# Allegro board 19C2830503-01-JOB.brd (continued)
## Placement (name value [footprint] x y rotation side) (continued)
C715  0.1uF  [C0402]  70.59 68.93 0 bottom
C716  0.1uF  [C0402]  47.24 68.58 270 bottom
C717  0.1uF  [C0402]  47.24 69.85 270 bottom
C718  27pF  [C0402]  152.53 66.67 270 bottom
C719  27pF  [C0402]  148.46 66.67 90 bottom
C720  0.1uF  [C0402]  144.02 131.57 0 bottom
C721  47uF  [C0805]  28.7 65.66 270 bottom
C722  1000pF  [C0402]  20.95 71.75 180 top
C723  0.1uF  [C0402]  22.23 71.75 0 top
C724  1uF  [C0603]  12.19 59.44 90 bottom
C725  0.1uF  [C0402]  89.41 56.39 0 bottom
C726  0.1uF  [C0402]  88.01 56.39 0 bottom
C727  100uF  [C1206-1]  31.75 60.71 270 bottom
C728  470uF  [C_2P_244_287X177_H110]  27.69 61.09 0 top
C729  1uF  [C0603]  13.21 58.04 270 top
C730  0.1uF  [C0402]  145.85 57.86 270 top
C731  1uF  [C0603]  13.21 56.52 270 top
C732  0.1uF  [C0402]  34.04 52.96 0 bottom
C733  2.2uF  [C0603]  113.03 50.42 180 bottom
C734  0.1uF  [C0402]  114.55 50.16 180 bottom
C735  0.1uF  [C0402]  61.09 49.4 270 bottom
C736  0.1uF  [C0402]  72.34 49.28 270 bottom
C737  0.1uF  [C0402]  64.85 48.77 90 bottom
C738  0.1uF  [C0402]  49.66 48.39 270 bottom
C739  0.1uF  [C0402]  41.53 47.62 180 bottom
C740  0.1uF  [C0402]  53.47 47.75 180 bottom
C741  0.1uF  [C0402]  126.27 47.25 180 bottom
C742  0.1uF  [C0402]  97.41 47.12 0 bottom
C743  0.1uF  [C0402]  88.27 47.12 0 bottom
C744  0.1uF  [C0402]  85.6 47.12 0 bottom
C745  0.1uF  [C0603]  22.35 47.12 270 bottom
C746  0.1uF  [C0402]  75.9 46.29 180 bottom
C747  0.1uF  [C0402]  53.34 45.85 180 bottom
C748  0.1uF  [C0402]  41.53 45.59 180 bottom
C749  0.1uF  [C0603]  128.4 45.21 90 bottom
C750  0.1uF  [C0402]  97.28 45.09 180 bottom
C751  0.1uF  [C0402]  88.27 44.83 0 bottom
C752  0.1uF  [C0402]  85.72 44.76 180 bottom
C753  0.1uF  [C0402]  105.79 44.07 270 bottom
C754  0.1uF  [C0402]  53.34 44.01 0 bottom
C755  0.1uF  [C0402]  64.85 43.94 0 bottom
C756  0.01uF  [C0402]  102.62 43.56 90 bottom
C757  0.01uF  [C0402]  100.33 43.56 270 bottom
C758  0.1uF  [C0402]  75.9 44.07 180 bottom
C759  0.1uF  [C0402]  62.23 43.31 0 bottom
C760  0.1uF  [C0402]  64.64 42.24 270 bottom
C761  0.01uF  [C0402]  102.62 42.16 90 bottom
C762  47uF  [C0805]  110.62 42.04 270 bottom
C763  0.1uF  [C0402]  49.73 41.91 270 bottom
C764  0.01uF  [C0402]  38.86 40.77 270 bottom
C765  100uF  [C1206-1]  116.97 41.27 0 bottom
C766  0.01uF  [C0402]  102.62 40.77 90 bottom
C767  4.7uF  [C1206-1]  125.6 39.75 90 bottom
C768  0.1uF  [C0402]  41.27 39.75 90 bottom
C769  0.1uF  [C0402]  33.15 39.75 90 bottom
C770  0.1uF  [C0402]  84.18 39.67 270 bottom
C771  0.1uF  [C0402]  72.11 39.67 270 bottom
C772  0.1uF  [C0402]  95.99 39.65 270 bottom
C773  47uF  [C0805]  110.62 39.62 270 bottom
C774  0.1uF  [C0402]  54.99 39.43 180 bottom
C775  1uF  [C0603]  131.44 41.53 90 bottom
C776  0.1uF  [C0402]  143 40.89 180 bottom
C777  0.1uF  [C0402]  73.99 38.42 0 bottom
C778  10uF  [C0603]  41.27 38.1 90 bottom
C779  47uF  [C0805]  110.62 37.21 270 bottom
C780  22uF  [C0805]  88.65 37.21 0 bottom
C781  22uF  [C0805]  76.96 37.21 0 bottom
C782  0.1uF  [C0402]  85.72 37.08 0 bottom
C783  0.1uF  [C0402]  33.15 36.96 90 bottom
C784  0.01uF  [C0402]  102.62 36.58 90 bottom
C785  22uF  [C0805]  52.83 36.45 0 bottom
C786  22uF  [C0805]  49.4 36.2 0 bottom
C787  10uF  [C0603]  41.27 36.32 90 bottom
C788  0.1uF  [C0402]  74.24 36.13 180 bottom
C789  22uF  [C0805]  65.48 35.94 0 bottom
C790  0.1uF  [C0402]  96.39 35.81 270 bottom
C791  0.22uF  [C0603]  126.49 35.43 0 bottom
C792  2.2uF  [C0603]  32.77 35.43 270 bottom
C793  0.1uF  [C0402]  102.62 35.18 270 bottom
C794  0.01uF  [C0402]  102.62 33.78 90 bottom
C795  470uF  [C_2P_244_287X177_H110]  109.09 33.53 90 bottom
C796  20pF  [C0402]  66.17 111.51 180 top
C797  20pF  [C0402]  63.37 111.51 0 top
C798  10uF  [C0603]  134.21 80.34 180 top
C799  0.1uF  [C0402]  132.56 79.96 0 top
C800  1uF  [C0402]  129.9 69.8 0 top
C801  22uF  [C0805]  132.46 69.72 270 top
C802  0.1uF  [C0402]  54.05 109.55 180 top
C803  0.01uF  [C0402]  55.73 109.8 90 top
C804  1000pF  [C0402]  55.73 108.41 270 top
C805  0.1uF  [C0402]  67.56 113.54 180 top
C806  0.01uF  [C0402]  68.96 113.54 180 top
C807  1000pF  [C0402]  70.36 113.54 0 top
C808  0.1uF  [C0402]  67.31 108.71 0 bottom
C809  0.01uF  [C0402]  68.58 108.71 0 bottom
C810  1000pF  [C0402]  65.91 108.71 180 bottom
C811  0.01uF  [C0402]  67.56 111.51 0 top
C812  0.1uF  [C0402]  68.96 111.51 0 top
C813  1000pF  [C0402]  70.36 111.51 180 top
C814  330pF  [C0402]  54.48 148.59 90 bottom
C815  330pF  [C0402]  130.45 32.38 270 bottom
C816  0.01uF  [C0402]  65.35 96.9 0 bottom
C817  0.01uF  [C0402]  78.23 84.33 270 bottom
C818  0.01uF  [C0402]  77.67 75.95 180 bottom
C819  0.01uF  [C0402]  39.37 67.69 270 top
C820  0.01uF  [C0402]  65.94 75.39 90 bottom
C821  0.01uF  [C0402]  80.77 85.98 270 bottom
C822  0.01uF  [C0402]  80.77 90.93 270 bottom
C823  0.01uF  [C0402]  78.74 89.15 90 bottom
C825  0.01uF  [C0402]  69.72 74.96 0 bottom
C826  0.01uF  [C0402]  68.02 75.49 90 bottom
C827  0.1uF  [C0402]  171.58 147.96 0 top
C828  10pF  [C0402]  169.8 155.57 90 top
C829  0.01uF  [C0402]  55.75 138.05 270 top
C830  0.01uF  [C0402]  131.06 43.05 90 bottom
C831  220uF  [C_2P_114_138X118]  73.03 138.56 0 bottom
C832  1000uF  [C_2P_244_295X177]  115.54 135.89 90 bottom
C833  220uF  [C_2P_114_138X118]  106.83 53.9 180 top
C834  220uF  [C_2P_114_138X118]  39.27 33.43 180 bottom
C835  0.1uF  [C0402]  29.72 134.37 270 bottom
C836  0.1uF  [C0402]  43.18 134.49 270 bottom
C837  0.1uF  [C0402]  30.48 146.3 270 bottom
C838  0.1uF  [C0402]  43.03 126.9 270 bottom
C839  0.1uF  [C0402]  162.05 107.31 270 top
C840  0.1uF  [C0402]  162.05 105.92 270 top
C841  1uF  [C0402]  31.14 128.4 90 bottom
C842  1uF  [C0402]  43.81 142.49 0 bottom
C843  0.1uF  [C0402]  43 147.57 0 top
C844  0.1uF  [C0402]  156.62 102.26 180 bottom
CN1  POWER MODULE_5223957-3  [POWERMODULE_2P_5223957-3]  27.5 169.96 270 top
CN2  PH_3x1V_2.00mm  [HD_3X1P_79_D]  169.67 128.65 270 top
CN3  BB_60x2V_S0.5mm  [BB_60X2P_20_2225X285_F]  35.32 144.45 90 top
CN4  COAXIEL_3V  [HS_UFL-R-SMT-1]  73.84 129.41 180 top
CN5  COAXIEL_3V  [HS_UFL-R-SMT-1]  47.5 138.56 270 top
CN6  COAXIEL_3V  [HS_UFL-R-SMT-1]  47.5 143.13 270 top
CN7  PH_6x1V_2.00mm  [HD_6X1P_79_D]  153.16 128.78 90 top
CN8  PH_3x1V_2.00mm  [HD_3X1P_79_D]  167 147.83 90 top
CN9  PH_2x1V_2.00mm  [HD_2X1P_79_H236_D]  146.81 124.59 90 top
CN10  COAXIEL_3V  [HS_UFL-R-SMT-1]  60.35 119.13 0 top
CN11  COAXIEL_4V  [COAXIAL_4P_MM8030-2610]  96.98 125.73 180 top
CN12  COAXIEL_4V  [COAXIAL_4P_MM8030-2610]  100.03 125.73 180 top
CN13  COAXIEL_4V  [COAXIAL_4P_MM8030-2610]  56.9 124.59 180 top
CN15  PH_2x1V_2.00mm  [HD_2X1P_79_H236_D]  74.8 120.02 270 top
CN16  RJ45_2x1_W/XFMR&LED  [RJ45_28P_RTB-19GB9J1A]  170.74 85.7 90 top
CN17  PH_4x2V_2.54mm  [HD_4X2P_100_D]  22.4 57.66 270 top
CN18  RF_5H  [RF-SMAC037]  177.1 40.71 90 top
CN19  PH_4x1V_2.0mm  [HD_4X1P_79_H264]  26.67 33.91 0 top
CN20  PH_4x1V_2.0mm  [HD_4X1P_79_H264]  35.31 33.91 0 top
CN21  PH_3x1V_2.54mm  [HD_3X1P_100_H320_D]  142.75 32.77 0 top
CN22  PH_5x2V_S1.27mm  [HD_5X2P_50_H235]  159.89 39.12 0 top
CN23  COAXIEL_3V  [HS_UFL-R-SMT-1]  73.84 124.84 0 top
CN24  PH_2x1V_2.00mm  [HD_2X1P_79_H236_D]  173.23 151.89 90 top
D1  TPD4S012DRYR  [SON_6P_20_59X39]  169.16 164.72 270 top
D3  KPA-1606EC  [LED_2P_KPA-1606EC]  179.2 157.82 270 top
D4  KP-1608MGC  [LED_0603]  170.69 157.75 90 top
D5  KPA-1606QBC-D  [LED_2P_KPA-1606QBC-D]  179.2 154.14 270 top
D6  KP-1608EC  [LED_0603]  175.01 140.22 270 top
D7  NL/SBU05U20LPS-7  [DIODE_2P_36_40X27]  111.12 116.33 270 top
D8  BZX84-C12  [SOT-23]  21.72 50.29 180 top
D9  PMEG1020EH  [DIODE_2P_146_106X61_ANODE2]  136.91 109.09 180 bottom
D10  ASD500V  [DIODE_2P_78_79X55]  11.01 36.69 90 top
D11  PMEG1020EH  [DIODE_2P_146_106X61_ANODE2]  148.97 158.62 0 bottom
D14  TPD2EUSB30DRTR  [SOT_TPD2EUSB30DRTR]  161.95 111.81 270 bottom
DBG_D1  KPBA-3010ESGC  [LED_2P_KPBA-3010ESGC]  179.01 149.76 90 top
DBG_D2  KPA-1606QBC-D  [LED_2P_KPA-1606QBC-D]  179.2 145 270 top
DBG_D3  KPA-1606QBC-D  [LED_2P_KPA-1606QBC-D]  179.2 141.06 270 top
DC_IN1  JACK_3H  [PJ_3P_2DC-0005]  16.64 44.96 270 top
DIMM1  SODIMMDDR3_204  [DDR3_204P_DDRSK-20401-TP65]  117.6 78.7 90 top
EEPROM1  ST_M24M01-RMN6TP  [SOIC_8P_50_193X236]  129.29 100.33 90 top
EMU1  BB_60V_S0.5mm  [BB_30X2P_20_838X285_F]  96.77 145.93 270 top
ESD1  -  [AMC-ESD-B]  160 175.36 0 top
FAN1  WB_4V_2.00mm  [WF_4P_79_BOX_D_721-81-04TW0]  16.44 57.28 270 top
FM1  Fiducial  [FIDUCIAL]  28.59 163.97 0 top
FM2  Fiducial  [FIDUCIAL]  167.65 36.95 0 top
FM3  Fiducial  [FIDUCIAL]  28.57 163.96 180 bottom
FM4  Fiducial  [FIDUCIAL]  167.64 36.96 180 bottom
FTDI_USB  MINIUSB_5H  [USB-UH51543]  174.54 165.39 90 top
GPS1  GNS_TC6000G  [BGA_36P_60_394X366]  147.07 43.49 90 top
H1  -  [H35P7-MTH]  138.89 166.98 0 top
H2  -  [H35P7-MTH]  138.89 124.49 0 top
H7  H107x17-NPTH  [H107X17-NPTH]  159 34.01 0 top
H8  -  [H27P35-MTH]  176.85 32.46 0 top
J1  ATCA_160H  [ATCA_160P_384312]  7.9 127.06 270 top
J2  ATCA_160H  [ATCA_160P_384312]  7.9 152.06 270 top
L1  22uH  [INDUCTOR_2P_267_270X265]  116.2 162.56 0 top
L2  3.3uH  [CHOKE_2P_238_287X260]  128.52 161.06 180 top
L3  0.47uH  [CHOKE_2P_238_287X260]  128.24 145.44 180 top
L4  0.2uH  [CHOKE_2P_238_287X260]  65.15 146.94 0 top
L5  0.47uH  [CHOKE_2P_238_287X260]  78.18 137.82 90 top
L6  0.47uH  [CHOKE_2P_238_287X260]  85.6 137.79 90 top
L7  0.47uH  [CHOKE_2P_238_287X260]  26.29 102.24 180 top
L8  3.3uH  [CHOKE_2P_238_287X260]  26.29 94.87 180 top
L9  1.5uH  [INDUCTOR_2P_183_205X193]  29.34 69.6 0 top
L10  0.082uH  [L0603]  171.83 43.31 180 top
L11  3.6nH  [L0402]  169.93 39.24 0 top
L12  0.47uH  [CHOKE_2P_238_287X260]  119.51 35.31 0 top
LCD1  LCD-Module_17P  [LCD_17P_NHD-C12832A1Z]  65.91 163.32 0 top
MCU  W_4V_2.54mm  [WF_4P_100_D_744-81-04TW20]  157.86 126.92 270 top
NAND1  MICRON_MT29F4G08ABBDAHC:D  [BGA_63P_31_512X413_C14]  38.58 157.84 0 bottom
NOR1  NUMONYX_N25Q128A11ESF40F  [SOIC_16P_50_406X406]  141.15 138.56 180 bottom
NOREF  -  []  37.72 18.29 0 top
NOREF#2  -  []  89.87 32.87 180 bottom
NOREF#3  -  []  174.24 64.52 180 bottom
NOREF#4  -  []  149.5 37 180 bottom
NOREF#5  -  []  166.75 65.53 180 bottom
NOREF#6  -  []  168.02 57.66 180 bottom
OSC1  32.768KHz  [OSC-4SD]  168.53 138.56 180 top
OSC2  25MHz  [OSC_6P_50_203X132]  102.36 117.6 90 top
OSC3  19.2MHz_15pF  [OSC_4P_236X157_382X295_H161]  52.45 118.49 0 top
OSC4  32.768KHz  [OSC-4SD]  144.65 53.59 0 top
PB1  30_100MHz  [L0805]  162 118.08 270 top
PHY1  MARVELL_88E1111-B2-BAB1C000  [BGA_117P_39_551X394]  144.15 74.1 0 bottom
PHY2  MARVELL_88E1111-B2-BAB1C000  [BGA_117P_39_551X394]  144.15 98.49 0 bottom
PMBUS1  PH_5x1V_2.54mm  [HD_5X1P_100_D]  149.86 129.03 90 top
PWR  DTSA-63R-V  [SW_2P_DTSA-63K-V_D]  176.75 134.16 90 top
Q1  TI_TPS73701DRBT  [QFN_8P_26_118X118]  165.74 169.67 0 top
Q2  TI_TPS74701DRCT  [QFN10P_20_118X118_TP94X65V5]  108.33 163.45 0 top
Q3  MMBT3904LT1G  [SOT-23]  176.46 156.62 90 top
Q4  MMBT3904LT1G  [SOT-23]  176.47 152.11 270 top
Q5  MMBT3904LT1G  [SOT-23]  176.6 143.86 270 top
Q6  MICROCHIP_MCP9700AT-E/LT  [SC-70_5P]  121.28 118.36 180 top
Q7  TI_TPS73701DRBT  [QFN_8P_26_118X118]  143.26 115.44 0 top
Q8  TI_TPS73701DRBT  [QFN_8P_26_118X118]  149.99 115.44 0 top
Q9  MMBT3904LT1G  [SOT-23]  25.4 47.62 90 top
Q10  TLV1117-33CDCY  [SOT-223]  120.02 171.63 0 bottom
Q11  MMBT3904LT1G  [SOT-23]  177.1 158.4 90 bottom
Q12  MMBT3904LT1G  [SOT-23]  173.55 157.51 90 bottom
Q13  APL431LBAI-TRG  [SOT-23]  78.61 158.67 0 bottom
Q14  MMBT3904LT1G  [SOT-23]  177.61 151.92 90 bottom
Q15  MICROCHIP_MCP9700AT-E/LT  [SC-70_5P]  124.94 150.5 90 bottom
Q16  MMBT3904LT1G  [SOT-23]  177.48 145.64 270 bottom
Q17  MICROCHIP_MCP9700AT-E/LT  [SC-70_5P]  68.45 143.64 0 bottom
Q18  MMBT3904LT1G  [SOT-23]  175.3 142.21 270 bottom
Q19  SI4435DDY-T1-GE3  [SOIC_8P_50_193X236]  11.81 50.42 0 top
Q20  2N7002  [SOT-23]  21.72 49.66 180 bottom
Q21  MICROCHIP_MCP9700AT-E/LT  [SC-70_5P]  116.92 34.04 180 bottom
R1  10M  [R1206]  38.48 174.5 90 top
R2  10M  [R1206]  150.5 174.5 270 top
R3  1K  [R0402]  162.23 171.04 90 bottom
R4  10K  [R0402]  163.58 171.02 270 bottom
R5  NL/0  [R0402]  153.92 174.12 90 top
R6  NL/0  [R0402]  155.32 174.12 90 top
R7  10K  [R0402]  104.39 173.99 0 top
R8  82.5K  [R0603]  113.67 173.99 0 top
R9  0  [R0402]  143.74 172.47 180 top
R10  1.87K  [R0603]  105.03 172.34 270 top
R11  10K  [R0402]  113.79 171.45 0 top
R12  22  [R0402]  133.32 171.42 270 top
R13  31.6K  [R0402]  124.84 170.69 270 top
R14  10K  [R0402]  126.24 170.69 90 top
R15  56.2K  [R0402]  133.32 169.52 90 top
R16  1K  [R0402]  160.66 169.16 180 top
R17  22.6K  [R0603]  105.03 170.69 270 top
R18  0  [R0402]  108.71 168.15 270 top
R19  17.4K  [R0402]  164.85 166.5 0 top
R20  10K  [R0402]  166.75 166.5 180 top
R21  10K  [R0402]  133.32 167.59 270 top
R22  1.69K  [R0603]  125.6 167 270 top
R23  3.57K  [R0603]  104.9 166.88 270 top
R24  10K  [R0402]  173.23 155.07 0 top
R25  1K  [R0402]  43.81 162.69 180 top
R26  0  [R0402]  168.66 161.93 0 top
R27  22  [R0402]  43.81 161.29 0 top
R28  10K  [R0402]  109.35 159.66 270 top
R29  4.7K  [R0402]  43.81 159.51 180 top
R30  56  [R0402]  177.8 158.69 90 top
R31  510  [R0402]  175.13 158.57 90 top
R32  100  [R0402]  88.52 157.48 180 top
R33  100  [R0402]  90.83 157.35 0 top
R34  4.7K  [R0402]  27.58 156.74 180 top
R35  0  [R0402]  29.57 156.74 180 top
R36  4.7K  [R0402]  88.52 155.96 0 top
R37  10  [R0402]  90.83 155.96 0 top
R38  4.7K  [R0402]  102.49 155.96 0 top
R39  0  [R0402]  165.86 155.57 180 top
R40  10K  [R0402]  167.89 155.57 0 top
R41  0  [R0402]  29.57 155.42 180 top
R42  4.7K  [R0402]  88.52 154.56 0 top
R43  10  [R0402]  90.83 154.56 0 top
R44  10  [R0402]  102.49 154.56 180 top
R45  0  [R0402]  165.86 152.78 180 top
R46  0  [R0402]  167.89 154.18 180 top
R47  10  [R0402]  90.81 153.29 0 top
R48  4.7K  [R0402]  134.75 153.29 0 top
R49  10  [R0402]  102.49 153.16 180 top
R50  4.7K  [R0402]  105.16 153.16 180 top
R51  0  [R0402]  165.86 154.18 180 top
R52  0  [R0402]  167.89 152.78 0 top
R53  10  [R0402]  88.52 151.89 180 top
R54  0  [R0402]  90.81 151.89 180 top
R55  10  [R0402]  41.4 152.4 180 top
R56  4.7K  [R0402]  102.49 151.77 0 top
R57  10  [R0402]  105.16 151.77 180 top
R58  4.75K  [R0402]  107.19 151.77 180 top
R59  10K  [R0402]  169.8 151.38 180 top
R60  10  [R0402]  41.4 151.13 180 top
R61  4.75K  [R0402]  88.52 150.5 0 top
R62  10  [R0402]  90.81 150.5 0 top
R63  10  [R0402]  102.49 150.37 0 top
R64  10  [R0402]  105.16 150.37 180 top
R65  1K  [R0402]  135.61 149.76 180 top
R66  10  [R0402]  90.81 149.1 0 top
R67  10  [R0402]  102.49 148.97 0 top
R68  10  [R0402]  105.16 148.97 0 top
R69  1K  [R0402]  40.94 145.26 180 top
R70  56  [R0402]  177.22 148.21 180 top
R71  10  [R0402]  90.81 147.7 0 top
R72  10  [R0402]  102.49 147.57 180 top
R73  10  [R0402]  105.16 147.57 180 top
R75  0  [R0402]  145.92 146.69 180 top
R76  510  [R0402]  177.11 146.69 0 top
R77  1K  [R0402]  71.75 149.86 180 top
R78  10  [R0402]  90.81 146.3 0 top
R79  10  [R0402]  102.49 146.18 180 top
R80  10  [R0402]  105.16 146.18 180 top
R81  10K  [R0402]  87.6 149.07 0 top
R82  10K  [R0402]  76.17 149.33 180 top
R83  10K  [R0402]  168.4 132.97 180 top
R84  8.2K  [R0402]  167.13 39.5 0 top
R85  2K  [R0402]  114.15 145.69 90 top
R86  0  [R0402]  145.92 145.54 180 top
R87  10  [R0402]  90.81 144.91 0 top
R89  10  [R0402]  102.49 144.78 180 top
R90  10  [R0402]  105.16 144.78 180 top
R91  100  [R0402]  167.13 42.29 180 top
R92  10K  [R0402]  113.89 143.92 180 top
R93  10K  [R0402]  112.14 143.64 270 top
R94  10  [R0402]  90.81 143.51 0 top
R96  10  [R0402]  102.49 143.38 180 top
R97  10  [R0402]  105.16 143.38 180 top
R98  0  [R0402]  145.57 144.15 180 top
R100  22  [R0402]  166.62 142.75 0 top
R103  10  [R0402]  90.81 142.11 0 top
R104  10  [R0402]  102.49 141.99 180 top
R105  22.6K  [R0603]  113.92 141.6 180 top
R106  2K  [R0402]  49.66 144.78 90 top
R109  10  [R0402]  90.81 140.72 0 top
R110  120  [R0402]  176.53 140.52 270 top
R111  10  [R0402]  177.93 140.51 90 top
R112  4.75K  [R0402]  102.49 140.34 0 top
R113  8.06K  [R0402]  120.27 140.13 90 top
R114  2.49K  [R0402]  115.54 140.11 270 top
R115  2.49K  [R0402]  116.94 140.11 270 top
R116  0  [R0402]  122.91 140.11 90 top
R117  0  [R0402]  58.8 143.13 90 top
R121  10K  [R0402]  50.16 142.11 270 top
R122  10K  [R0402]  49.78 142.37 180 bottom
R123  0  [R0402]  141.22 138.68 0 top
R128  22.6K  [R0603]  50.42 144.27 90 bottom
R129  0  [R0402]  148.46 136.91 90 top
R130  0  [R0402]  152.02 136.91 270 top
R131  0  [R0402]  150.22 136.8 0 top
R134  2.49K  [R0402]  51.56 140.08 180 top
R135  2.49K  [R0402]  53.34 139.62 270 top
R136  8.06K  [R0402]  58.29 139.57 180 top
R137  750  [R0402]  112.52 134.75 0 top
R138  750  [R0402]  114.55 134.75 0 top
R139  750  [R0402]  116.59 134.75 0 top
R140  750  [R0402]  118.62 134.75 0 top
R145  0  [R0402]  51.56 138.63 180 top
R146  100  [R0402]  110.49 134.75 0 top
R147  NL/2K  [R0402]  112.52 133.35 180 top
R148  NL/2K  [R0402]  114.55 133.35 180 top
R149  NL/2K  [R0402]  116.59 133.35 180 top
R150  NL/2K  [R0402]  118.62 133.35 180 top
R151  100K  [R0402]  108.71 134.49 90 top
R152  100  [R0402]  170.43 134.37 180 top
R157  10  [R0402]  94.36 133.73 90 top
R158  10  [R0402]  95.76 133.73 90 top
R159  4.99K  [R0402]  110.49 133.35 180 top
R161  8.2K  [R0402]  170.43 132.97 0 top
R162  0  [R0402]  140.39 132.94 180 top
R163  0  [R0402]  142.29 132.94 180 top
R164  0  [R0402]  135.56 132.66 270 top
R165  0  [R0402]  136.96 132.66 270 top
R166  0  [R0402]  138.35 132.66 270 top
R170  100  [R0402]  102.62 132.21 270 top
R171  NL/4.99K  [R0402]  104.01 132.21 90 top
R172  100K  [R0402]  108.71 132.21 270 top
R173  2K  [R0402]  123.06 132.08 0 top
R174  10K  [R0402]  130.3 131.95 270 top
R175  10K  [R0402]  131.7 131.95 270 top
R176  10K  [R0402]  133.1 131.95 270 top
R178  0  [R0402]  140.39 131.55 180 top
R179  0  [R0402]  142.29 131.55 180 top
R180  0  [R0402]  72.9 128.78 180 bottom
R181  0  [R0402]  72.9 127.38 180 bottom
R182  0  [R0402]  72.9 125.98 180 bottom
R183  0  [R0402]  72.9 124.59 180 bottom
R184  0  [R0402]  72.52 122.43 180 top
R185  0  [R0402]  72.52 121.03 180 top
R188  0  [R0402]  47.5 133.73 0 top
R189  0  [R0402]  47.5 135 0 top
R190  0  [R0402]  50.67 136.4 270 top
R191  2K  [R0402]  123.06 130.68 0 top
R192  0  [R0402]  136.22 130.45 0 top
R193  0  [R0402]  52.07 136.4 270 top
R195  100  [R0402]  102.62 130.18 270 top
R196  NL/4.99K  [R0402]  104.01 130.18 90 top
R197  2K  [R0402]  123.06 129.29 0 top
R198  1K  [R0402]  82.04 131.83 180 top
R200  33  [R0402]  69.93 119.51 90 top
R201  100  [R0402]  102.62 128.14 270 top
R202  4.99K  [R0402]  104.01 128.14 90 top
R203  0  [R0402]  123.06 127.89 180 top
R204  33  [R0402]  68.66 119.51 90 top
R206  0  [R0402]  123.06 126.49 180 top
R207  0  [R0402]  68.07 134.37 90 top
R208  10.2K  [R0402]  102.62 126.11 90 top
R209  1.5K  [R0402]  104.01 126.11 270 top
R210  33  [R0402]  67.39 119.51 90 top
R212  90.9K  [R0402]  123.06 125.09 0 top
R213  0  [R0402]  41.53 120.02 180 top
R214  10K  [R0402]  66.55 131.44 270 top
R215  33  [R0402]  66.04 119.51 90 top
R216  1K  [R0402]  105.16 124.33 180 top
R217  8.2K  [R0402]  171.32 123.95 0 top
R218  90.9K  [R0402]  123.06 123.7 180 top
R219  1K  [R0402]  65.28 134.37 270 top
R220  4.7K  [R0402]  168.91 123.52 270 top
R221  10K  [R0402]  43.43 120.02 0 top
R222  10K  [R0402]  144.78 123.19 270 top
R223  NL/0  [R0402]  102.74 122.94 0 top
R224  4.7K  [R0402]  120.4 122.56 180 top
R225  0  [R0402]  64.14 130.56 90 top
R226  0  [R0402]  123.06 122.3 180 top
R227  560  [R0402]  43.43 118.62 180 top
R228  10K  [R0402]  48.77 131.7 180 bottom
R229  100  [R0402]  99.44 123.06 180 top
R231  NL/0  [R0402]  102.74 121.54 0 top
R232  4.7K  [R0402]  154.05 121.54 0 top
R233  100  [R0402]  171.32 121.16 180 top
R234  0  [R0402]  123.06 120.9 180 top
R235  0  [R0402]  49.02 124.33 270 top
R237  NL/1K  [R0402]  144.4 120.27 0 top
R238  0  [R0402]  119 119.76 180 top
R239  49.9  [R0402]  60.07 124.71 180 top
R240  49.9  [R0402]  60.07 123.32 180 top
R241  3.16K  [R0402]  60.07 122.02 180 top
R242  0  [R0402]  61.72 121.59 270 top
R243  0  [R0402]  123.32 119.25 270 top
R244  0  [R0402]  124.71 119.25 270 top
R245  0  [R0402]  127.51 119.25 90 top
R246  0  [R0402]  128.91 119.25 90 top
R247  0  [R0402]  130.3 119.25 90 top
R248  4.7K  [R0402]  133.1 119.25 90 top
R249  4.7K  [R0402]  134.62 119.25 90 top
R250  0  [R0402]  131.7 119.2 90 top
R251  10K  [R0402]  150.88 119.18 270 top
R252  0  [R0402]  50.42 124.33 270 top
R253  0  [R0402]  51.82 124.33 270 top
R255  10K  [R0402]  144.4 118.87 0 top
R256  49.9  [R0402]  53.21 124.33 270 bottom
R257  49.9  [R0402]  54.61 124.33 270 bottom
R258  5.6K  [R0402]  56.01 124.33 270 bottom
R259  3.16K  [R0402]  57.4 124.33 90 bottom
R260  NL/10K  [R0402]  45.97 117.37 0 top
R261  1K  [R0402]  45.97 114.83 180 top
R262  0  [R0402]  136.09 118.64 90 top
R263  0  [R0402]  137.49 118.64 90 top
R264  0  [R0402]  60.02 129.03 180 top
R265  0  [R0402]  60.02 127.63 180 top
R267  1K  [R0402]  119 117.22 0 top
R268  1M  [R0603]  116.97 116.59 180 top
R269  0  [R0402]  112.52 116.46 90 top
R270  10K  [R0402]  115.32 116.46 90 top
R271  1.3K  [R0402]  109.7 116.1 270 top
R272  49.9  [R0402]  95.12 120.52 0 top
R273  49.9  [R0402]  95.12 119 0 top
R274  10K  [R0402]  21.34 113.16 180 top
R275  10K  [R0402]  23.62 113.03 180 top
R276  NL/10K  [R0402]  25.65 113.03 180 top
R277  0  [R0402]  95.12 117.6 0 top
R278  33  [R0402]  27.81 111.51 180 top
R279  150  [R0402]  29.72 111.51 0 top
R280  0  [R0402]  142.88 111.38 270 top
R281  10K  [R0402]  144.27 111.38 90 top
R282  100  [R0402]  17.91 110.87 90 top
R283  39.2K  [R0603]  149.86 110.74 0 top
R284  36.5K  [R0603]  151.51 110.74 0 top
R285  0  [R0402]  95.12 116.21 0 top
R286  33  [R0402]  27.81 109.98 180 top
R287  150  [R0402]  29.72 109.98 0 top
R288  100  [R0402]  31.88 109.98 90 top
R289  4.7K  [R0402]  152.91 109.73 270 top
R290  4.7K  [R0402]  154.18 109.73 90 top
R291  4.7K  [R0402]  158.37 109.73 90 top
R292  10K  [R0402]  16.26 109.6 0 top
R293  10  [R0402]  73.41 108.71 270 bottom
R294  10  [R0402]  75.18 108.71 270 bottom
R295  100  [R0402]  17.91 108.84 270 top
R296  1.3K  [R0402]  16.26 108.08 180 top
R297  4.7K  [R0402]  134.37 107.57 180 top
R298  475  [R0402]  27.81 107.44 0 top
R299  510  [R0402]  87.5 112.52 270 top
R300  10K  [R0402]  90.04 112.52 90 top
R301  0  [R0402]  92.33 112.52 270 top
R302  5.6K  [R0402]  93.6 112.52 270 top
R303  3.16K  [R0402]  95.81 114.5 90 top
R304  10K  [R0402]  17.7 106.68 180 top
R305  0  [R0402]  84.45 111.89 90 top
R306  4.7K  [R0402]  134.37 106.04 180 top
R307  10K  [R0402]  61.72 110.62 270 top
R308  NL/10K  [R0402]  61.72 108.71 270 top
R309  22  [R0402]  71.37 108.71 90 top
R310  3K  [R0402]  73.41 108.71 90 top
R311  10  [R0402]  75.18 108.71 270 top
R312  4.7K  [R0402]  76.45 108.71 90 top
R313  4.7K  [R0402]  77.85 108.71 90 top
R314  10  [R0402]  79.25 108.71 270 top
R315  10  [R0402]  81.53 108.71 90 top
R316  10  [R0402]  82.8 108.71 90 top
R317  0  [R0402]  124.46 104.52 0 top
R318  10K  [R0402]  14.99 104.01 90 top
R319  NL/10K  [R0402]  60.2 110.62 270 top
R320  1K  [R0402]  34.32 104.44 270 top
R321  10K  [R0402]  60.2 108.71 270 top
R322  NL/0  [R0402]  134.24 102.24 0 top
R323  0  [R0402]  134.24 100.84 180 top
R324  4.7K  [R0402]  124.46 100.2 0 top
R325  0  [R0402]  134.24 99.44 180 top
R326  NL/0  [R0402]  134.24 98.04 0 top
R327  220  [R0402]  153.8 98.04 0 top
R328  1K  [R0402]  34.8 92.2 90 top
R329  10K  [R0402]  14.86 92.08 270 top
R330  4.7K  [R0402]  26.62 90.2 90 top
R331  4.7K  [R0402]  27.76 90.2 90 top
R332  4.7K  [R0402]  30.05 90.2 90 top
R333  220  [R0402]  153.8 89.66 0 top
R334  4.7K  [R0402]  35.66 89.03 0 top
R335  220  [R0402]  153.8 88.27 0 top
R336  4.7K  [R0402]  28.07 88.01 270 top
R337  4.7K  [R0402]  30.1 87.88 90 top
R338  0  [R0402]  32.51 87.88 270 top
R339  4.7K  [R0402]  33.78 87.88 90 top
R340  4.7K  [R0402]  35.69 87.88 0 top
R341  4.7K  [R0402]  35.69 86.61 0 top
R342  750  [R0402]  17.14 86.36 0 top
R343  3.3K  [R0402]  18.8 86.11 270 top
R344  4.7K  [R0402]  35.69 85.47 0 top
R345  750  [R0402]  15.24 84.96 0 top
R346  1K  [R0402]  35.69 84.33 0 top
R347  NL/2K  [R0402]  18.8 84.07 270 top
R348  10  [R0402]  13.21 83.57 180 top
R349  750  [R0402]  15.24 83.57 0 top
R350  220  [R0402]  153.8 83.31 0 top
R351  1M  [R0603]  36.07 82.93 270 top
R352  10  [R0402]  17.4 82.04 90 top
R353  698  [R0402]  18.8 82.04 270 top
R354  0  [R0402]  35.69 81.41 180 top
R355  10  [R0402]  13.59 80.77 180 top
R356  750  [R0402]  15.62 80.77 0 top
R357  10  [R0402]  17.4 80.01 90 top
R358  2K  [R0402]  18.8 80.01 270 top
R359  1.3K  [R0402]  35.69 78.87 0 top
R360  75K  [R0402]  17.53 77.98 180 top
R361  75K  [R0402]  19.94 77.98 0 top
R362  4.7K  [R0402]  35.69 77.72 0 top
R363  4.7K  [R0402]  98.68 77.98 0 top
R364  10  [R0402]  101.6 77.85 180 top
R365  NL/4.99K  [R0402]  15.37 76.58 180 top
R366  4.7K  [R0402]  35.69 76.33 0 top
R367  10  [R0402]  98.68 76.33 180 top
R368  10  [R0402]  101.6 76.2 180 top
R369  22  [R0402]  104.78 76.2 0 top
R370  100  [R0402]  15.37 75.18 0 top
R371  220  [R0402]  153.8 74.68 0 top
R372  22  [R0402]  98.68 74.8 0 top
R373  22  [R0402]  101.6 74.68 180 top
R374  10  [R0402]  104.78 74.68 180 top
R375  10.2K  [R0402]  19.3 74.17 0 top
R376  1.5K  [R0402]  20.83 73.91 270 top
R377  10K  [R0402]  27.81 73.91 90 top
R378  0  [R0402]  30.48 73.91 90 top
R379  4.7K  [R0402]  31.75 73.91 270 top
R380  0  [R0402]  34.29 73.91 90 top
R381  4.7K  [R0402]  35.56 73.91 270 top
R382  220  [R0402]  153.8 73.28 0 top
R383  10  [R0402]  98.68 73.28 180 top
R384  10  [R0402]  101.6 73.41 180 top
R385  4.7K  [R0402]  104.78 73.41 180 top
R386  10K  [R0402]  23.7 64.59 270 top
R387  10  [R0402]  101.6 72.01 180 top
R388  10  [R0402]  98.68 71.63 180 top
R389  4.7K  [R0402]  104.78 72.01 180 top
R390  4.7K  [R0402]  104.78 70.48 180 top
R391  10  [R0402]  104.78 70.48 180 bottom
R393  10  [R0402]  104.78 69.09 180 bottom
R394  4.7K  [R0402]  104.78 69.09 180 top
R395  10K  [R0402]  19.68 71.75 90 top
R396  10  [R0402]  101.6 64.26 180 top
R397  1K  [R0402]  33.91 71.12 270 top
R398  10  [R0402]  101.59 62.99 180 top
R399  220  [R0402]  140.84 64.39 90 top
R400  220  [R0402]  139.45 64.39 90 top
R401  10  [R0402]  124.08 61.09 0 top
R402  10  [R0402]  124.08 59.69 0 top
R403  100K  [R0402]  135.86 61.37 270 top
R404  4.7K  [R0402]  139.85 57.45 90 top
R405  4.7K  [R0402]  138.33 57.48 90 top
R406  10K  [R0402]  28.45 55.12 270 top
R407  10K  [R0402]  29.84 55.12 270 top
R408  4.7K  [R0402]  152.15 54.36 180 top
R409  0  [R0402]  124.59 53.85 0 top
R410  NL/0  [R0402]  110.62 53.21 180 top
R411  4.7K  [R0402]  27.05 52.96 90 top
R412  4.7K  [R0402]  28.45 52.96 90 top
R413  4.7K  [R0402]  29.84 52.96 90 top
R414  4.7K  [R0402]  31.24 52.96 90 top
R415  4.7K  [R0402]  32.64 52.96 90 top
R416  4.7K  [R0402]  34.04 52.96 90 top
R417  4.7K  [R0402]  35.43 52.96 90 top
R418  4.7K  [R0402]  36.83 52.96 90 top
R419  1K  [R0402]  152.14 52.88 0 top
R420  4.7K  [R0402]  124.59 52.45 180 top
R421  4.7K  [R0402]  110.62 51.82 180 top
R422  4.7K  [R0402]  134.75 51.82 180 top
R423  22  [R0402]  149.35 51.18 90 top
R424  4.7K  [R0402]  124.59 50.93 180 top
R425  4.7K  [R0402]  38.35 52.45 270 top
R426  4.7K  [R0402]  39.75 52.45 270 top
R427  100K  [R0402]  25.27 50.8 90 top
R428  4.7K  [R0402]  110.62 50.42 180 top
R429  4.7K  [R0402]  134.75 50.42 180 top
R430  10K  [R0402]  152.15 51.44 0 bottom
R431  100K  [R0402]  18.54 49.66 0 top
R432  NL/0  [R0402]  110.62 49.02 180 top
R433  0  [R0402]  139.57 49.4 180 top
R434  100K  [R0402]  19.05 47.75 90 top
R435  1K  [R0402]  22.61 47.62 270 top
R436  100K  [R0402]  20.83 46.48 0 top
R437  100K  [R0402]  22.61 45.72 270 top
R438  220  [R0402]  35.94 47.5 180 bottom
R439  220  [R0402]  35.94 46.1 180 bottom
R440  100K  [R0402]  35.94 44.83 180 bottom
R441  1K  [R0402]  105.16 43.69 0 top
R442  1K  [R0402]  107.19 43.69 0 top
R443  39.2  [R0402]  100.33 43.56 0 top
R444  39.2  [R0402]  105.16 42.29 180 top
R445  39.2  [R0402]  100.33 42.16 0 top
R446  4.7K  [R0402]  27.05 41.66 270 top
R447  4.7K  [R0402]  28.45 41.66 270 top
R448  4.7K  [R0402]  29.84 41.66 270 top
R449  4.7K  [R0402]  31.24 41.66 270 top
R450  4.7K  [R0402]  34.04 41.63 270 top
R451  4.7K  [R0402]  35.43 41.63 270 top
R452  4.7K  [R0402]  36.83 41.63 270 top
R453  4.7K  [R0402]  38.23 41.63 270 top
R454  39.2  [R0402]  105.16 40.89 180 top
R455  39.2  [R0402]  102.62 40.77 180 top
R456  22.6K  [R0603]  135.89 40.13 270 top
R457  39.2  [R0402]  105.16 39.5 180 top
R458  39.2  [R0402]  100.33 39.37 0 top
R459  2  [R0402]  125.73 38.73 0 top
R460  10K  [R0402]  135.36 38.53 0 top
R461  10K  [R0402]  137.29 38.61 0 top
R462  39.2  [R0402]  105.16 38.1 180 top
R463  39.2  [R0402]  100.33 37.97 0 top
R464  39.2  [R0402]  102.62 37.97 180 top
R465  39.2  [R0402]  105.16 36.7 180 top
R466  39.2  [R0402]  100.33 36.58 0 top
R467  39.2  [R0402]  102.62 36.58 180 top
R468  0  [R0402]  125.6 36.32 0 top
R469  2K  [R0402]  134.75 36.2 270 top
R470  4.7K  [R0402]  100.33 35.18 0 top
R471  0  [R0402]  143.13 36.07 0 top
R472  1K  [R0402]  151.99 172.09 180 bottom
R473  100  [R0402]  93.98 170.56 270 bottom
R474  100  [R0402]  96.52 170.56 270 bottom
R475  100  [R0402]  99.06 170.56 270 bottom
R476  100  [R0402]  101.6 170.56 270 bottom
R477  4.7K  [R0402]  153.92 169.55 180 bottom
R479  10K  [R0402]  110.36 168.15 270 bottom
R480  22  [R0402]  149.61 167.64 0 bottom
R481  2.87K  [R0603]  108.33 167.51 0 bottom
R482  2.2K  [R0402]  150.75 164.97 90 bottom
R483  12.1K  [R0603]  160.15 164.08 0 bottom
R484  10K  [R0402]  150.75 162.94 270 bottom
R485  27  [R0402]  164.72 42.42 180 top
R487  NL/0  [R0402]  154.43 157.35 90 bottom
R488  NL/0  [R0402]  152.53 157.35 90 bottom
R489  NL/0  [R0402]  151.13 157.35 90 bottom
R490  22  [R0402]  134.37 157.35 180 bottom
R491  27  [R0402]  164.72 41.02 180 top
R492  120  [R0402]  171.14 155.57 0 bottom
R493  27  [R0402]  164.72 39.62 180 top
R494  510  [R0402]  176.71 155.45 180 bottom
R495  10K  [R0402]  159.89 154.94 270 bottom
R496  10K  [R0402]  158.5 154.94 270 bottom
R497  10K  [R0402]  157.1 154.94 270 bottom
R498  10K  [R0402]  155.7 154.94 270 bottom
R499  3.3K  [R0402]  154.43 154.94 270 bottom
R500  3.3K  [R0402]  153.16 154.94 270 bottom
R501  3.3K  [R0402]  151.76 154.94 270 bottom
R502  NL/10K  [R0402]  150.37 154.94 270 bottom
R503  NL/0  [R0402]  148.97 154.94 90 bottom
R504  510  [R0402]  174.02 154.61 180 bottom
R505  10K  [R0402]  73.66 157.73 0 bottom
R506  27  [R0402]  164.72 38.23 180 top
R507  10  [R0402]  178.82 153.99 90 bottom
R508  6.98K  [R0402]  75.56 157.28 270 bottom
R509  220  [R0603]  48.26 157.23 90 bottom
R510  510  [R0402]  176.4 153.85 270 bottom
R511  4.75K  [R0402]  134.75 153.29 180 bottom
R512  100  [R0402]  73.66 156.34 0 bottom
R513  27  [R0402]  164.72 36.83 180 top
R514  0  [R0402]  153.8 152.15 270 bottom
R515  0  [R0402]  152.4 152.15 270 bottom
R516  10  [R0402]  90.81 151.89 180 bottom
R517  4.75K  [R0402]  88.52 151.89 0 bottom
R518  33K  [R0402]  163.96 151.77 180 bottom
R519  4.75K  [R0402]  134.75 151.38 180 bottom
R520  10  [R0402]  90.81 150.5 180 bottom
R521  4.7K  [R0402]  154.43 149.73 270 bottom
R522  510  [R0402]  178.12 149.1 0 bottom
R523  10  [R0402]  90.81 149.1 0 bottom
R524  0  [R0402]  163.96 148.97 0 bottom
R525  510  [R0402]  176.53 148.77 270 bottom
R526  33K  [R0402]  163.96 147.7 180 bottom
R527  10  [R0402]  90.81 147.7 0 bottom
R528  10K  [R0402]  163.96 146.3 180 bottom
R529  10  [R0402]  90.81 146.3 0 bottom
R530  4.7K  [R0402]  136.65 145.54 270 bottom
R531  0  [R0402]  155.57 37.97 90 top
R532  10  [R0402]  90.81 144.91 0 bottom
R533  510  [R0402]  172.76 144.32 0 bottom
R534  10  [R0402]  178.89 143.6 90 bottom
R535  10  [R0402]  90.81 143.51 0 bottom
R536  0  [R0402]  20.95 109.85 270 bottom
R537  2  [R0402]  122.15 142.65 0 bottom
R538  1.3K  [R0603]  119.48 142.65 90 bottom
R539  10  [R0402]  90.81 142.11 0 bottom
R540  10K  [R0402]  86.87 144.78 270 bottom
R541  0  [R0402]  19.56 109.85 270 bottom
R542  10  [R0402]  90.81 140.72 0 bottom
R544  10K  [R0402]  75.72 143.99 270 bottom
R545  931  [R0402]  116.94 140.11 270 bottom
R546  10K  [R0402]  163.07 139.57 90 bottom
R547  0  [R0603]  119.48 139.22 90 bottom
R549  NL/0  [R0603]  16.51 108.33 180 bottom
R550  2  [R0402]  56.77 141.86 270 bottom
R551  1.3K  [R0402]  53.59 141.6 180 bottom
R553  931  [R0402]  51.56 140.08 180 bottom
R555  0  [R0402]  18.16 109.85 270 bottom
R557  4.7K  [R0402]  18.16 107.82 270 bottom
R558  10  [R0402]  134.49 133.73 0 bottom
R560  3K  [R0402]  123.06 132.08 0 bottom
R563  1.3K  [R0402]  123.06 130.68 0 bottom
R564  0  [R0402]  136.22 130.45 0 bottom
R566  499  [R0402]  123.06 129.29 0 bottom
R567  1K  [R0402]  85.47 130.3 0 bottom
R568  NL/0  [R0402]  103.76 129.16 270 bottom
R569  4.7K  [R0402]  66.04 119.51 90 bottom
R570  4.7K  [R0402]  83.06 126.24 180 bottom
R571  4.7K  [R0402]  67.44 119.51 90 bottom
R572  4.7K  [R0402]  83.08 127.63 180 bottom
R573  4.7K  [R0402]  119 122.56 0 bottom
R574  33  [R0402]  133.45 122 90 bottom
R575  4.7K  [R0402]  119 121.16 0 bottom
R576  4.7K  [R0402]  158.24 119.89 270 bottom
R577  4.7K  [R0402]  154.18 119.89 270 bottom
R578  4.7K  [R0402]  152.91 119.89 90 bottom
R579  0  [R0402]  134.62 119.25 90 bottom
R580  0  [R0402]  133.1 119.25 90 bottom
R581  10K  [R0402]  126.11 119.25 270 bottom
R582  2K  [R0402]  124.71 119.25 90 bottom
R583  2K  [R0402]  123.32 119.25 90 bottom
R584  5.6K  [R0402]  61.59 126.37 180 bottom
R585  NL/1K  [R0402]  150.88 119.18 90 bottom
R586  0  [R0402]  76.2 124.84 0 bottom
R587  4.7K  [R0402]  82.04 118.34 180 bottom
R588  4.99K  [R0402]  149.73 108.84 90 bottom
R589  0  [R0402]  148.34 108.84 90 bottom
R590  4.7K  [R0402]  145.67 108.84 90 bottom
R591  4.7K  [R0402]  140.08 108.84 90 bottom
R592  4.7K  [R0402]  138.68 108.84 90 bottom
R593  4.7K  [R0402]  144.27 108.84 90 bottom
R594  4.7K  [R0402]  142.88 108.84 90 bottom
R595  4.7K  [R0402]  141.48 108.84 90 bottom
R596  4.7K  [R0402]  145.67 106.55 270 bottom
R597  4.7K  [R0402]  144.27 106.55 270 bottom
R598  4.7K  [R0402]  142.88 106.55 270 bottom
R599  4.7K  [R0402]  141.48 106.55 270 bottom
R600  4.7K  [R0402]  140.08 106.55 270 bottom
R601  NL/4.7K  [R0402]  138.68 106.55 270 bottom
R602  4.99K  [R0402]  149.73 106.37 90 bottom
R603  10K  [R0402]  148.34 106.37 270 bottom
R604  4.7K  [R0402]  124.46 106.3 0 bottom
R605  10  [R0402]  96.39 117.47 270 bottom
R606  10  [R0402]  95.12 117.47 270 bottom
R607  0  [R0402]  77.85 108.71 270 bottom
R608  0  [R0402]  76.45 108.71 270 bottom
R609  22  [R0402]  61.72 108.71 90 bottom
R610  4.7K  [R0402]  124.46 104.78 0 bottom
R611  0  [R0402]  134.37 104.52 180 bottom
R612  10K  [R0402]  18.03 104.01 90 bottom
R613  0  [R0402]  163.32 103.12 90 bottom
R614  10  [R0402]  71.37 108.71 270 bottom
R615  10  [R0402]  69.98 108.71 270 bottom
R616  10K  [R0402]  57.4 108.71 90 bottom
R617  10K  [R0402]  58.8 108.71 90 bottom
R618  49.9  [R0402]  153.8 100.83 180 bottom
R619  10  [R0402]  81.53 108.71 90 bottom
R620  1K  [R0402]  66.55 97.92 90 bottom
R621  22  [R0402]  65.02 98.43 0 bottom
R622  0  [R0402]  60.41 98.92 90 bottom
R623  10K  [R0402]  69.93 98.43 180 bottom
R624  49.9  [R0402]  153.8 99.42 180 bottom
R625  1K  [R0402]  68 98.43 0 bottom
R626  49.9  [R0402]  153.8 98.04 180 bottom
R627  4.99K  [R0402]  134.24 98.04 180 bottom
R628  22  [R0402]  62.99 97.97 90 bottom
R629  4.7K  [R0402]  61.55 98.79 90 bottom
R630  49.9  [R0402]  153.8 96.65 180 bottom
R631  4.7K  [R0402]  134.24 96.65 0 bottom
R632  3K  [R0402]  57.91 93.5 0 bottom
R633  49.9  [R0402]  153.8 95.25 180 bottom
R634  4.99K  [R0402]  134.24 95.25 180 bottom
R635  3K  [R0402]  59 92.35 180 bottom
R636  49.9  [R0402]  153.8 93.85 180 bottom
R637  49.9  [R0402]  153.8 92.46 180 bottom
R638  3K  [R0402]  58.04 90.98 180 bottom
R639  10K  [R0402]  19.15 92 0 bottom
R640  240  [R0402]  87.05 91.44 0 bottom
R641  49.9  [R0402]  153.8 91.06 180 bottom
R642  0  [R0402]  147.45 90.3 0 bottom
R643  NL/10K  [R0402]  143.51 89.86 270 bottom
R644  0  [R0402]  141.99 89.86 90 bottom
R645  0  [R0402]  140.46 89.86 90 bottom
R646  0  [R0402]  138.94 89.86 270 bottom
R647  0  [R0402]  137.41 89.86 90 bottom
R648  4.7K  [R0402]  98.55 88.27 0 bottom
R649  3K  [R0402]  58.04 88.52 180 bottom
R650  4.7K  [R0402]  28.07 88.01 90 bottom
R651  4.7K  [R0402]  30.1 87.88 90 bottom
R652  10K  [R0402]  143.51 87.7 90 bottom
R653  0  [R0402]  141.99 87.7 90 bottom
R654  0  [R0402]  140.46 87.7 90 bottom
R655  0  [R0402]  138.94 87.7 90 bottom
R656  3K  [R0402]  57.02 86.87 0 bottom
R657  240  [R0402]  87.02 85.47 0 bottom
R658  0  [R0402]  47.27 79.76 0 bottom
R659  4.99K  [R0402]  149.73 84.45 90 bottom
R660  0  [R0402]  148.34 84.45 90 bottom
R661  4.7K  [R0402]  145.67 84.45 90 bottom
R662  4.7K  [R0402]  140.08 84.45 90 bottom
R663  4.7K  [R0402]  138.68 84.45 90 bottom
R664  4.7K  [R0402]  144.27 84.44 90 bottom
R665  4.7K  [R0402]  142.88 84.44 90 bottom
R666  4.7K  [R0402]  141.48 84.44 90 bottom
R667  3K  [R0402]  58.47 82.93 90 bottom
R668  10  [R0402]  35.74 89.05 0 bottom
R669  0  [R0402]  47.27 78.36 0 bottom
R670  10  [R0402]  35.74 87.66 0 bottom
R671  3K  [R0402]  55.98 81.64 180 bottom
R672  4.7K  [R0402]  145.67 82.16 270 bottom
R673  4.7K  [R0402]  144.27 82.16 270 bottom
R674  4.7K  [R0402]  142.88 82.16 270 bottom
R675  4.7K  [R0402]  141.48 82.16 270 bottom
R676  4.7K  [R0402]  140.08 82.16 270 bottom
R677  NL/4.7K  [R0402]  138.68 82.16 270 bottom
R678  4.99K  [R0402]  149.73 81.97 90 bottom
R679  10K  [R0402]  148.34 81.97 270 bottom
R680  49.9  [R0402]  153.8 81.91 180 bottom
R681  49.9  [R0402]  153.8 80.52 180 bottom
R682  100  [R0402]  24.26 80.52 180 bottom
R683  100  [R0402]  22.23 80.52 0 bottom
R684  240  [R0402]  85.52 79.96 270 bottom
R685  3K  [R0402]  57.02 80.44 180 bottom
R686  NL/4.99K  [R0402]  24.26 79.12 0 bottom
R687  NL/4.99K  [R0402]  22.23 79.12 180 bottom
R688  4.7K  [R0402]  35.69 78.87 0 bottom
R689  49.9  [R0402]  153.8 77.6 180 bottom
R690  22  [R0402]  101.6 79.12 180 bottom
R691  22  [R0402]  104.78 76.2 0 bottom
R692  22  [R0402]  101.6 77.85 180 bottom
R693  100  [R0402]  28.96 76.96 270 bottom
R694  4.99K  [R0402]  27.56 76.96 90 bottom
R695  49.9  [R0402]  153.8 76.2 180 bottom
R696  4.7K  [R0402]  101.6 76.2 180 bottom
R697  10  [R0402]  98.68 76.33 0 bottom
R698  3K  [R0402]  56.77 76.71 180 bottom
R699  22.6K  [R0402]  15.37 75.18 180 bottom
R700  49.9  [R0402]  153.8 74.68 180 bottom
R701  4.7K  [R0402]  104.78 74.68 180 bottom
R702  4.7K  [R0402]  101.6 74.68 180 bottom
R703  10  [R0402]  98.68 74.8 0 bottom
R704  4.99K  [R0402]  134.11 73.91 180 bottom
R705  49.9  [R0402]  153.8 73.28 180 bottom
R706  4.7K  [R0402]  101.6 73.41 180 bottom
R707  4.7K  [R0402]  98.68 73.28 180 bottom
R708  10  [R0402]  104.78 73.41 180 bottom
R709  4.7K  [R0402]  134.11 72.52 0 bottom
R710  49.9  [R0402]  153.8 71.88 180 bottom
R711  4.7K  [R0402]  101.6 72.01 180 bottom
R712  10  [R0402]  104.78 72.01 180 bottom
R713  4.7K  [R0402]  98.68 71.63 180 bottom
R714  4.7K  [R0402]  59.05 72.39 0 bottom
R715  4.99K  [R0402]  134.11 71.12 180 bottom
R716  240  [R0402]  71.12 74.93 90 bottom
R717  49.9  [R0402]  153.8 70.48 180 bottom
R718  10  [R0402]  101.6 70.48 180 top
R719  240  [R0402]  78.99 69.93 0 bottom
R720  4.7K  [R0402]  101.6 70.48 180 bottom
R721  4.7K  [R0402]  101.6 69.09 180 bottom
R722  10  [R0402]  101.6 69.09 180 top
R723  4.7K  [R0402]  101.6 66.93 180 bottom
R724  10  [R0402]  101.6 66.93 180 top
R725  0  [R0402]  150.5 66.67 0 bottom
R726  NL/10K  [R0402]  146.56 66.29 270 bottom
R727  0  [R0402]  145.03 66.29 90 bottom
R728  0  [R0402]  143.64 66.29 90 bottom
R729  0  [R0402]  142.11 66.29 270 bottom
R730  0  [R0402]  140.34 66.29 90 bottom
R731  4.7K  [R0402]  101.6 65.53 180 bottom
R732  10  [R0402]  101.6 65.53 180 top
R733  4.7K  [R0402]  145.92 131.57 270 bottom
R734  4.7K  [R0402]  101.6 64.26 180 bottom
R735  10K  [R0402]  146.56 64.07 90 bottom
R736  0  [R0402]  145.03 64.07 90 bottom
R737  0  [R0402]  143.64 64.13 90 bottom
R738  0  [R0402]  142.11 64.13 90 bottom
R739  4.7K  [R0402]  101.59 62.99 180 bottom
R740  10  [R0402]  9.32 61.77 180 bottom
R741  10  [R0402]  98.65 68.35 180 bottom
R742  0  [R0402]  9.32 60.38 0 bottom
R743  10  [R0402]  98.65 66.95 180 bottom
R744  4.7K  [R0402]  67.58 49.66 180 bottom
R745  4.7K  [R0402]  74.24 48.77 0 bottom
R746  4.7K  [R0402]  68.4 48.13 90 bottom
R747  4.7K  [R0402]  70.18 47.62 0 bottom
R748  4.7K  [R0402]  74.24 47.37 180 bottom
R749  4.7K  [R0402]  64.72 47.12 0 bottom
R750  10K  [R0402]  101.85 46.36 180 bottom
R751  4.7K  [R0402]  70.18 46.1 0 bottom
R752  4.7K  [R0402]  74.24 45.97 180 bottom
R753  4.7K  [R0402]  64.72 45.72 0 bottom
R754  4.7K  [R0402]  67.26 45.59 270 bottom
R755  0  [R0603]  131.57 45.21 270 bottom
R756  10  [R0402]  110.36 44.45 90 bottom
R757  10  [R0402]  109.09 44.45 90 bottom
R758  4.7K  [R0402]  74.24 44.45 0 bottom
R759  0  [R0402]  10.92 40.13 0 bottom
R760  931  [R0402]  134.62 43.31 0 bottom
R761  1.3K  [R0603]  128.4 43.43 270 bottom
R762  10K  [R0402]  149.35 44.58 90 bottom
R763  39.2  [R0402]  105.16 42.29 180 bottom
R764  0  [R0402]  10.92 38.61 0 bottom
R765  39.2  [R0402]  100.33 42.16 0 bottom
R766  2.49K  [R0402]  135.38 41.66 90 bottom
R767  2.49K  [R0402]  133.99 41.66 90 bottom
R768  8.06K  [R0402]  129.16 41.66 270 bottom
R769  1K  [R0402]  39.88 42.67 180 bottom
R770  1K  [R0402]  37.47 42.16 180 bottom
R771  240  [R0603]  45.97 41.4 270 bottom
R772  39.2  [R0402]  105.16 40.89 180 bottom
R773  10K  [R0402]  19.94 32.26 90 bottom
R774  0  [R0402]  146.81 43.05 90 bottom
R775  39.2  [R0402]  100.33 40.77 0 bottom
R776  240  [R0603]  87.76 40.77 90 bottom
R777  240  [R0603]  92.96 40.51 180 bottom
R778  240  [R0603]  74.75 40.39 90 bottom
R779  39.2  [R0402]  105.16 39.5 180 bottom
R780  10K  [R0402]  18.54 32.26 90 bottom
R781  39.2  [R0402]  102.62 39.37 180 bottom
R782  39.2  [R0402]  100.33 39.37 0 bottom
R783  1K  [R0402]  116.97 39.12 180 bottom
R784  240  [R0603]  62.61 38.99 0 bottom
R785  10K  [R0402]  33.15 38.35 180 bottom
R786  39.2  [R0402]  105.16 38.1 180 bottom
R787  10K  [R0402]  17.14 32.26 90 bottom
R788  39.2  [R0402]  102.62 37.97 180 bottom
R789  39.2  [R0402]  100.33 37.97 0 bottom
R790  39.2  [R0402]  105.16 36.7 180 bottom
R791  10K  [R0402]  15.75 32.26 90 bottom
R792  39.2  [R0402]  100.33 36.58 0 bottom
R793  10K  [R0402]  14.35 32.26 90 bottom
R794  39.2  [R0402]  100.33 35.18 0 bottom
R795  39.2  [R0402]  100.33 33.78 0 bottom
R796  4.7K  [R0402]  153.54 68.58 90 bottom
R797  4.7K  [R0402]  151.89 89.41 90 bottom
R798  100  [R0402]  64.77 111.51 90 top
R799  100  [R0402]  78.36 111.12 90 top
R800  NL/100  [R0402]  76.96 111.12 270 top
R801  NL/0  [R0402]  92.46 128.27 270 bottom
R802  2.2  [R0805]  57.53 148.08 270 bottom
R803  2.2  [R0805]  127.61 32.64 90 bottom
R804  NL/4.7K  [R0402]  44.83 146.94 0 bottom
R805  NL/4.7K  [R0402]  44.83 145.54 180 bottom
R806  10  [R0402]  102.74 121.54 180 bottom
R807  0  [R0402]  105.89 119.63 0 top
R808  NL/0  [R0402]  109.63 117.98 90 top
R809  10  [R0402]  90.42 108.71 0 bottom
R810  NL/0  [R0402]  45.34 125.48 270 bottom
R811  0  [R0402]  45.77 127.28 0 bottom
R812  NL/0  [R0402]  107.67 159.33 180 bottom
R813  NL/0  [R0402]  160.68 101.68 270 bottom
R814  4.7K  [R0402]  153.42 105.16 90 bottom
R815  10K  [R0402]  101.09 129.54 90 top
R816  10K  [R0402]  65.53 131.44 180 bottom
R817  10K  [R0402]  93.5 123.75 0 top
RR1  240  [R0402]  63.34 68.97 270 bottom
RST_MCU1  PT-004-E1  [SW_2P_388_236X138]  161.04 45.09 0 top
SIM1  SIM_8H  [SIM_8P_FMS006Z-2001-1]  175.65 56.94 90 top
SOC  W_4V_2.54mm  [WF_4P_100_D_744-81-04TW20]  164.72 126.87 270 top
SOC_USB  USB3.0_9H  [USB_9P_UEA1112C-4HK1-4H]  169.12 111.16 90 top
SOCKET1  TI_SOC_K2H_Socket  [TI_SOC_K2H_SOCKET]  72.52 82.42 0 top
SW1  ESD104EZ  [SW_4X2P_100_398X378]  97.79 169.93 180 top
TP1  -  [TP-S40]  145.34 172.42 0 top
TP2  -  [TP28]  134.7 170.28 0 top
TP3  -  [TP28]  113.28 169.42 0 top
TP4  -  [TP28]  121.16 165.61 0 top
TP5  -  [TP28]  106.17 165.48 0 top
TP6  -  [TP-S40]  154.31 157.23 0 top
TP7  -  [TP28]  151.38 157.1 0 top
TP8  -  [TP28]  29.59 153.97 0 top
TP9  -  [TP28]  166.12 151.64 0 top
TP10  -  [TP-S40]  132.84 149.61 90 top
TP11  -  [TP28]  69.26 149.84 270 top
TP12  -  [TP28]  73.66 130.43 90 bottom
TP13  -  [TP28]  133.22 133.86 0 top
TP14  -  [TP28]  131.44 133.73 0 top
TP15  -  [TP28]  134.49 133.73 0 top
TP16  -  [TP28]  49.4 136.78 180 top
TP17  -  [TP28]  74.93 126.62 270 bottom
TP18  -  [TP28]  74.93 130.43 90 bottom
TP19  -  [TP28]  74.93 129.16 90 bottom
TP20  -  [TP28]  74.93 127.89 270 bottom
TP21  -  [TP28]  134.37 132.59 0 top
TP22  -  [TP28]  47.12 132.46 180 top
TP23  -  [TP28]  49.4 135.89 180 top
TP24  -  [TP28]  72.39 130.43 270 bottom
TP25  -  [TP28]  134.42 131.44 0 top
TP26  -  [TP28]  53.67 136.65 180 top
TP27  -  [TP28]  70.82 117.86 90 top
TP28  -  [TP28]  68.71 117.88 90 top
TP29  -  [TP28]  67.39 117.88 90 top
TP30  -  [TP28]  66.07 117.88 90 top
TP31  -  [TP28]  103.5 124.21 180 top
TP32  -  [TP28]  65.28 131.06 270 top
TP33  -  [TP28]  118.75 122.68 270 top
TP34  -  [TP28]  100.84 123.19 0 top
TP35  -  [TP28]  48.46 125.96 0 top
TP36  -  [TP28]  97.92 123.19 0 top
TP37  -  [TP28]  58.93 123.57 0 top
TP38  -  [TP28]  139.88 111.07 0 top
TP39  -  [TP28]  146.69 110.74 0 top
TP40  -  [TP28]  91.19 113.03 270 top
TP41  -  [TP28]  74.9 106.17 0 top
TP42  -  [TP28]  69.85 115.19 0 top
TP43  -  [TP28]  74.32 106.86 0 top
TP44  -  [TP28]  80.34 110.82 0 top
TP45  -  [TP28]  28.96 89.53 0 top
TP46  -  [TP28]  98.17 80.65 0 top
TP47  -  [TP28]  98.17 79.38 0 top
TP48  -  [TP28]  28.19 75.31 0 top
TP49  -  [TP28]  128.02 67.44 0 top
TP50  -  [TP28]  33.66 69.09 0 top
TP51  -  [TP28]  90.93 54.23 0 top
TP52  -  [TP28]  92.33 54.23 0 top
TP53  -  [TP28]  54.61 55.88 0 top
TP54  -  [TP28]  68.45 54.1 0 top
TP55  -  [TP28]  56.13 55.88 0 top
TP56  -  [TP28]  69.98 54.1 0 top
TP57  -  [TP28]  13.66 55.19 0 top
TP58  -  [TP28]  108.46 47.88 270 top
TP59  -  [TP-S40]  115.06 38.1 0 top
TP60  -  [TP28]  125.09 153.8 0 bottom
TP61  -  [TP28]  147.19 106.17 180 bottom
TP62  -  [TP28]  80.39 108.46 180 bottom
TP64  -  [TP28]  58.37 99.32 180 bottom
TP65  -  [TP28]  59.33 98.41 180 bottom
TP66  -  [TP28]  81.41 98.5 180 bottom
TP67  -  [TP28]  60.48 97.4 180 bottom
TP68  -  [TP28]  60.33 92.08 180 bottom
TP69  -  [TP28]  98.3 89.41 180 bottom
TP70  -  [TP28]  56.52 88.42 180 bottom
TP71  -  [TP28]  87.53 88.43 180 bottom
TP72  -  [TP28]  89.51 88.44 180 bottom
TP73  -  [TP28]  57.48 85.39 180 bottom
TP74  -  [TP28]  56.49 84.33 180 bottom
TP75  -  [TP28]  147.19 81.66 180 bottom
TP76  -  [TP28]  59.51 80.42 180 bottom
TP77  -  [TP28]  85.51 78.48 180 bottom
TP78  -  [TP28]  87.52 80.42 180 bottom
TP79  -  [TP28]  55.37 77.22 180 bottom
TP80  -  [TP28]  89.53 78.42 180 bottom
TP81  -  [TP28]  87.52 75.39 180 bottom
TP82  -  [TP28]  86.45 75.38 180 bottom
TP83  -  [TP28]  86.58 73.42 180 bottom
TP84  -  [TP28]  89.41 73.89 180 bottom
TP85  -  [TP28]  88.47 73.8 180 bottom
TP86  -  [TP28]  57.53 75.44 180 bottom
TP87  -  [TP28]  87.54 73.52 180 bottom
TP88  -  [TP28]  69.52 69.44 180 bottom
TP89  -  [TP28]  69.51 66.42 180 bottom
TP90  -  [TP28]  55.58 56.24 180 bottom
TP91  -  [TP28]  68.5 67.41 180 bottom
TP92  -  [TP28]  56.72 56.26 180 bottom
TP93  -  [TP28]  140.84 64.26 180 bottom
TP94  -  [TP28]  102.49 44.96 180 bottom
TP95  -  [TP28]  147.07 41.27 90 bottom
TP96  -  [TP28]  31.11 38.35 180 bottom
TP97  -  [TP28]  39.37 36.96 90 bottom
U1  TI_TPS54620RGY  [QFN_14P_20_138X138_TP79]  109.98 172.21 180 top
U2  TI_TPS54620RGY  [QFN_14P_20_138X138_TP79]  130.05 168.72 180 top
U3  FTDI_FT2232HL  [QFP_64P_20_472X472]  152.65 165.35 90 top
U4  TI_SN74LVC2G125DCUR  [SOIC_8P_20_79X122]  167.64 158.75 0 top
U5  TI_TXS0108EPWR  [SOIC_20P_26_256X252]  139.95 155.96 270 top
U6  TI_SN74AHCT1G08DCKR  [SC-70_5P]  169.54 148.84 180 top
U7  14_TI_LM3S2D93-IQC80_0  [QFP_100P_20_630X630]  155.96 147.19 270 top
U8  TI_UCD74111RVF  [QFN40P20_276X197T209X130V21]  118.85 146.2 90 top
U9  TI_UCD7242RSJT  [QFN_32P_20_236X236_UDC7242]  81.89 146.79 270 top
U10  TI_UCD74120RVF  [QFN40P20_276X197T209X130V21]  54.25 144.98 90 top
U11  TI_SN74LVC1G32DCK  [SC70_5P]  103.25 137.92 270 top
U12  TI_SN74LVC2G157DCUT  [SOIC_8P_20_79X122]  144.65 137.92 270 top
U13  TI_UCD9090RGZT  [QFN_48P_20_276X276_TP202V25]  129.41 125.35 0 top
U14  TI_CDCM6208V2RGZT  [QFN_48P_20_276X276_TP161V16]  52.98 130.76 0 top
U15  TI_CDCM6208V2RGZT  [QFN_48P_20_276X276_TP161V16]  66.75 125.07 270 top
U16  TI_UCD9244RGCR  [QFN_64P_20_354X354_TP167V25]  112.14 124.46 270 top
U17  TI_SN74LVC2G157DCUT  [SOIC_8P_20_79X122]  78.44 122.3 270 top
U18  TI_MAX3221ECPWR  [SOIC_16P_26_197X252]  156.21 114.81 180 top
U19  TI_CDCM6208V2RGZT  [QFN_48P_20_276X276_TP161V16]  88.87 118.64 90 top
U20  IDT_5V41068APGGI  [SOIC_16P_26_197X252]  22.73 109.47 270 top
U21  TI_SN74LVC2G157DCUT  [SOIC_8P_20_79X122]  78.61 116.21 270 top
U22  TI_PCA9517DR  [SOIC_8P_50_193X236]  129.41 106.3 90 top
U23  TI_UCD7242RSJT  [QFN_32P_20_236X236_UDC7242]  16.76 98.43 0 top
U24  TI_TMS320TCI6638  [BGA_1517P_39_1575X1575_H125]  72.52 82.42 180 top
U25  TI_UCD9244RGCR  [QFN_64P_20_354X354_TP167V25]  27.3 81.28 0 top
U26  TI_SN74LVC1G19DCKR  [SC-70_6P]  107.06 63.75 270 top
U27  TI_UCD74106RGMT  [QFN_13P_20_UCD74106]  23.11 68.33 0 top
U28  TI_SN74LVC2G125DCUR  [SOIC_8P_20_79X122]  106.93 61.09 270 top
U29  TI_DAC8550IBDGKT  [SOIC_8P_26_118X193]  130.43 65.41 180 top
U30  TI_SN74LVC2G157DCUT  [SOIC_8P_20_79X122]  106.93 58.42 90 top
U31  TI_PCA9306DCUT  [SOIC_8P_20_79X122]  139.34 60.93 0 top
U32  TI_SN74AVC4T245PWR  [SOIC_16P_26_197X252]  129.12 58.46 90 top
U33  TI_TXS4555RGTR  [QFN_16P_20_118X118_TP59]  144.78 60.96 0 top
U34  TI_PCA9517DR  [SOIC_8P_50_193X236]  129.5 51.5 90 top
